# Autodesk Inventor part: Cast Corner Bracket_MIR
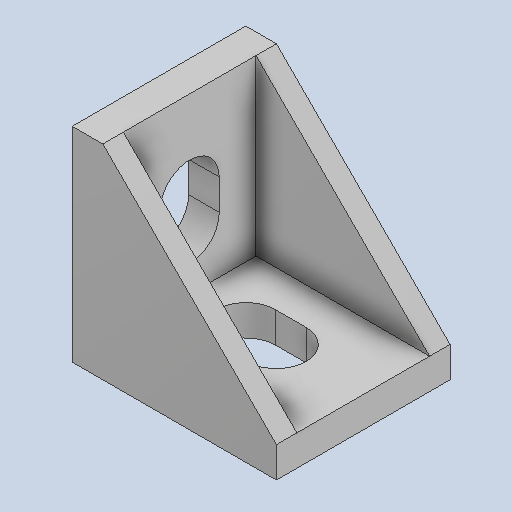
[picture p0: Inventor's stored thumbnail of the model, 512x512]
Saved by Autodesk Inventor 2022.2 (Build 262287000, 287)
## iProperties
Created: 2019-09
Part Number: Cast Corner Bracket_MIR
Material: SolidWorks Materials|6061-T6 (SS)
Document SubType Name: Modeling
Designer: 18907419
Density: 2.7 g/cm^3
Appearance: Default
Author: 18907419
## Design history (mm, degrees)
feature "Solido1"
node "Solido2"
